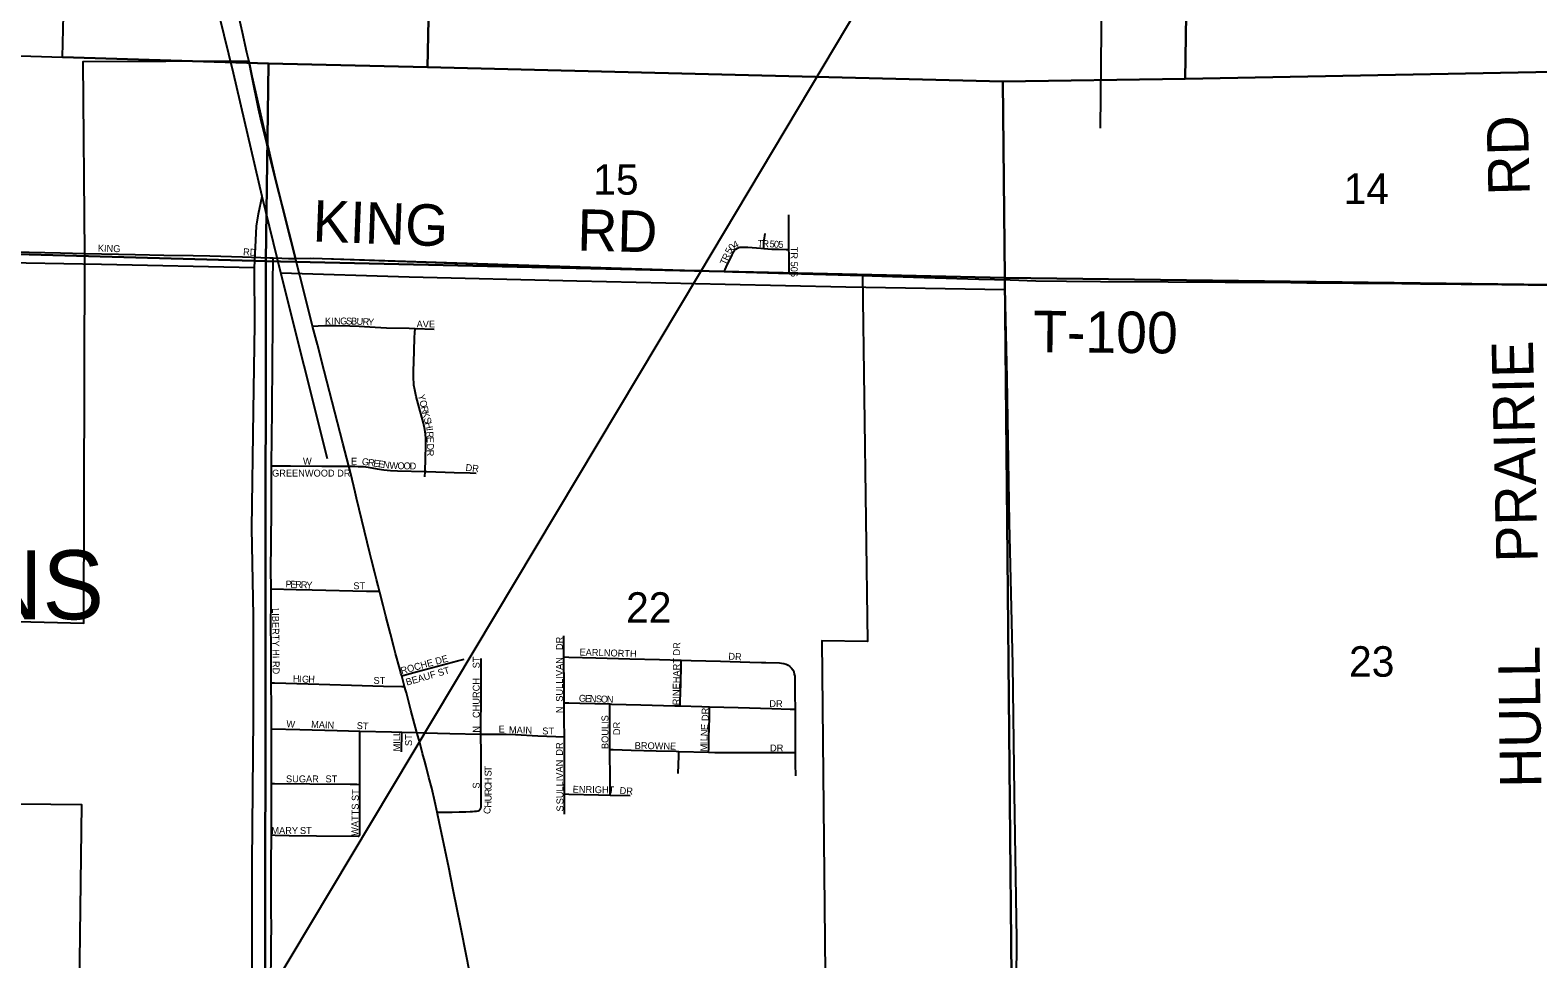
# Model space of a CAD drawing. Extents: x 1443599 to 1910620, y 1028088 to 1361369.
# Drawn here: x 1635252 to 1646176, y 1262715 to 1269443 of the extents above; entities that cross this region are included whole.
import ezdxf

# ---------------------------------------------------------------- set-up
doc = ezdxf.new("R2010")
doc.units = 0
for name, color, linetype in [('GM_X_City_Street', 7, 'Continuous'), ('GM_X_City_Street_Text', 7, 'Continuous'), ('GM_X_Corporation', 7, 'Continuous'), ('GM_X_Corporation_Text', 7, 'Continuous'), ('GM_X_Minor_River', 7, 'Continuous'), ('GM_X_Rail_Line', 7, 'Continuous'), ('GM_X_Section', 7, 'Continuous'), ('GM_X_Section_Text', 7, 'Continuous'), ('GM_X_State_Route', 7, 'Continuous'), ('GM_X_Township_Road', 7, 'Continuous'), ('GM_X_Township_Road_Text', 7, 'Continuous'), ('GM_X_Township_Subdivision', 7, 'Continuous'), ('GM_X_Township_Subdivision_Text', 7, 'Continuous')]:
    doc.layers.add(name, color=color, linetype=linetype)

msp = doc.modelspace()

# ---------------------------------------------------------------- linework, layer by layer
at = {"layer": 'GM_X_City_Street'}
for points in [[(1635648, 1267824), (1636013, 1267818), (1636220, 1267814), (1636433, 1267810), (1636555, 1267808), (1636790, 1267801), (1636988, 1267794), (1637012, 1267793)], [(1637002, 1266286), (1637002, 1266294), (1637004, 1266491), (1637006, 1266689), (1637006, 1266787), (1637009, 1266952), (1637008, 1267067), (1637010, 1267280), (1637010, 1267395), (1637011, 1267527), (1637011, 1267642), (1637012, 1267757), (1637012, 1267793)], [(1637299, 1267299), (1637339, 1267301), (1637388, 1267303), (1637470, 1267303), (1637569, 1267302), (1637635, 1267299), (1637751, 1267291), (1637833, 1267287), (1637998, 1267283), (1638041, 1267282)], [(1638114, 1266246), (1638120, 1266435), (1638120, 1266484), (1638117, 1266517), (1638113, 1266549), (1638101, 1266597), (1638071, 1266709), (1638050, 1266789), (1638039, 1266837), (1638033, 1266870), (1638031, 1266886), (1638030, 1266920), (1638030, 1266970), (1638035, 1267118), (1638038, 1267217), (1638040, 1267250), (1638041, 1267282)], [(1638041, 1267282), (1638180, 1267278)], [(1636998, 1265397), (1636997, 1265538), (1636999, 1265719), (1637001, 1265982), (1637001, 1266163), (1637002, 1266286)], [(1637002, 1266286), (1637138, 1266286), (1637365, 1266284), (1637560, 1266285)], [(1637560, 1266285), (1637604, 1266284), (1637629, 1266283), (1637652, 1266282), (1637668, 1266281), (1637701, 1266277), (1637767, 1266266), (1637815, 1266258), (1637864, 1266254), (1637913, 1266251), (1638114, 1266246)], [(1638113, 1266207), (1638114, 1266246)], [(1638114, 1266246), (1638127, 1266246), (1638325, 1266239), (1638441, 1266235), (1638484, 1266234)], [(1636999, 1264716), (1636998, 1264766), (1636998, 1264946), (1636997, 1265160), (1636998, 1265275), (1636998, 1265397)], [(1636998, 1265397), (1637180, 1265392), (1637295, 1265389), (1637688, 1265379), (1637753, 1265378), (1637783, 1265378)], [(1639120, 1264902), (1639120, 1265038), (1639119, 1265055)], [(1637944, 1264765), (1637978, 1264775), (1638059, 1264797), (1638348, 1264875), (1638397, 1264887)], [(1638518, 1264344), (1638518, 1264460), (1638519, 1264543), (1638519, 1264692), (1638519, 1264792), (1638519, 1264842), (1638520, 1264875), (1638520, 1264892)], [(1639120, 1264902), (1639155, 1264901), (1639352, 1264896), (1639598, 1264888), (1639811, 1264883), (1639970, 1264879)], [(1639122, 1264571), (1639121, 1264692), (1639120, 1264890), (1639120, 1264902)], [(1639962, 1264548), (1639963, 1264580), (1639967, 1264711), (1639970, 1264842), (1639970, 1264879)], [(1639970, 1264879), (1640041, 1264877), (1640254, 1264871), (1640467, 1264865), (1640550, 1264863), (1640582, 1264861), (1640681, 1264859), (1640697, 1264858), (1640713, 1264855), (1640729, 1264850), (1640744, 1264843), (1640757, 1264834), (1640768, 1264822), (1640778, 1264809), (1640785, 1264794), (1640789, 1264778), (1640792, 1264762), (1640793, 1264745), (1640793, 1264630), (1640794, 1264524)], [(1636999, 1264716), (1637022, 1264715), (1637266, 1264708), (1637580, 1264699), (1637812, 1264691), (1637946, 1264689), (1637965, 1264689)], [(1637001, 1264381), (1637000, 1264453), (1637000, 1264535), (1636999, 1264716)], [(1639122, 1264571), (1639154, 1264570), (1639236, 1264568), (1639453, 1264562)], [(1639123, 1264324), (1639122, 1264444), (1639122, 1264571)], [(1639453, 1264232), (1639453, 1264434), (1639453, 1264532), (1639453, 1264562)], [(1639453, 1264562), (1639465, 1264561), (1639678, 1264556), (1639923, 1264549), (1639962, 1264548)], [(1639962, 1264548), (1640120, 1264543), (1640175, 1264542)], [(1640168, 1264212), (1640169, 1264237), (1640170, 1264318), (1640175, 1264462), (1640175, 1264510), (1640175, 1264542)], [(1640175, 1264542), (1640382, 1264535), (1640627, 1264529), (1640758, 1264525), (1640794, 1264524)], [(1640794, 1264524), (1640795, 1264417), (1640794, 1264210)], [(1637000, 1263986), (1637000, 1264042), (1637000, 1264206), (1637001, 1264381)], [(1637001, 1264381), (1637207, 1264376), (1637476, 1264369), (1637640, 1264365)], [(1637640, 1264365), (1637871, 1264359), (1637944, 1264357)], [(1637640, 1263979), (1637640, 1264037), (1637640, 1264348), (1637640, 1264365)], [(1637943, 1264216), (1637944, 1264357)], [(1637944, 1264357), (1638055, 1264355)], [(1638055, 1264355), (1638114, 1264353), (1638293, 1264348), (1638518, 1264344)], [(1638200, 1263779), (1638311, 1263779), (1638360, 1263780), (1638392, 1263781), (1638409, 1263781), (1638441, 1263782), (1638456, 1263783), (1638471, 1263784), (1638487, 1263785), (1638499, 1263788), (1638508, 1263792), (1638513, 1263798), (1638518, 1263807), (1638519, 1263817), (1638520, 1263833), (1638520, 1263849), (1638520, 1263866), (1638520, 1263882), (1638520, 1263897), (1638519, 1263960), (1638519, 1264008), (1638519, 1264073), (1638520, 1264154), (1638519, 1264235), (1638518, 1264308), (1638518, 1264344)], [(1638518, 1264344), (1638522, 1264344), (1638702, 1264342), (1638768, 1264340), (1638931, 1264330), (1639062, 1264326), (1639123, 1264324)], [(1639124, 1263910), (1639124, 1263979), (1639123, 1264178), (1639123, 1264324)], [(1639454, 1263901), (1639454, 1263931), (1639454, 1264045), (1639453, 1264191), (1639453, 1264232)], [(1639453, 1264232), (1639477, 1264231), (1639607, 1264227), (1639787, 1264223), (1639934, 1264219), (1639952, 1264218)], [(1639948, 1264059), (1639951, 1264185), (1639952, 1264218)], [(1639952, 1264218), (1640168, 1264212)], [(1640168, 1264212), (1640212, 1264211), (1640794, 1264210)], [(1640794, 1264210), (1640796, 1264127), (1640798, 1264041)], [(1637000, 1263613), (1637000, 1263729), (1637000, 1263926), (1637000, 1263986)], [(1637000, 1263986), (1637022, 1263986), (1637279, 1263983), (1637570, 1263980), (1637618, 1263980), (1637640, 1263979)], [(1637637, 1263607), (1637638, 1263608), (1637639, 1263609), (1637639, 1263611), (1637640, 1263613), (1637640, 1263677), (1637641, 1263776), (1637640, 1263939), (1637640, 1263979)], [(1639124, 1263910), (1639156, 1263909), (1639369, 1263904), (1639454, 1263901)], [(1639124, 1263764), (1639124, 1263910)], [(1639454, 1263901), (1639599, 1263898)], [(1636999, 1262839), (1637000, 1262938), (1636999, 1263069), (1636999, 1263432), (1637000, 1263580), (1637000, 1263613)], [(1637000, 1263613), (1637028, 1263612), (1637128, 1263610), (1637328, 1263607), (1637630, 1263605), (1637632, 1263605), (1637634, 1263605), (1637636, 1263606), (1637637, 1263607)], [(1636997, 1262472), (1636999, 1262839)]]:
    msp.add_lwpolyline(points, dxfattribs=at)
at = {"layer": 'GM_X_Corporation'}
for points in [[(1634297, 1265182), (1635641, 1265146), (1635648, 1267824), (1635636, 1269216), (1636837, 1269220), (1636858, 1269113), (1637030, 1268362), (1637175, 1267789), (1637285, 1267792), (1637450, 1267786), (1640280, 1267695), (1640751, 1267681), (1641282, 1267666), (1641318, 1265015), (1640989, 1265020), (1641015, 1262371)], [(1635610, 1262515), (1635626, 1263830), (1634274, 1263845)]]:
    msp.add_lwpolyline(points, dxfattribs=at)
at = {"layer": 'GM_X_Minor_River'}
for points in [[(1643037, 1271626), (1643026, 1270663), (1643011, 1269435), (1643004, 1268733)], [(1637406, 1266337), (1637069, 1267686), (1636933, 1268239), (1636726, 1269132), (1636521, 1269970), (1636439, 1270297)], [(1636861, 1262358), (1636861, 1262486), (1636861, 1263412), (1636871, 1264461), (1636871, 1265199), (1636859, 1265836), (1636871, 1266685), (1636879, 1267311), (1636877, 1267722), (1636893, 1268023), (1636906, 1268113), (1636933, 1268239)], [(1636877, 1267722), (1635768, 1267745), (1634949, 1267760)], [(1637069, 1267686), (1637999, 1267655), (1639213, 1267628), (1640288, 1267604), (1641163, 1267583), (1642314, 1267564), (1642328, 1266921), (1642346, 1265877), (1642369, 1264847), (1642383, 1263912), (1642399, 1262858), (1642393, 1262232)]]:
    msp.add_lwpolyline(points, dxfattribs=at)
at = {"layer": 'GM_X_Rail_Line'}
msp.add_lwpolyline([(1628024, 1247385), (1629402, 1249688), (1632328, 1254610), (1636988, 1262473), (1640104, 1267683), (1644118, 1274411), (1645800, 1277195), (1647368, 1279858), (1650566, 1285234), (1651910, 1287492), (1654331, 1291581), (1655752, 1293976)], dxfattribs=at)
at = {"layer": 'GM_X_Section'}
for points in [[(1643716, 1274422), (1648915, 1274524), (1648809, 1269125), (1647557, 1269165), (1643620, 1269091), (1643662, 1271713), (1643687, 1273004)], [(1635549, 1271885), (1638187, 1271829), (1638130, 1269174), (1636978, 1269202), (1635486, 1269247), (1635517, 1270567)], [(1638187, 1271829), (1643662, 1271713), (1643620, 1269091), (1642299, 1269070), (1638130, 1269174)], [(1631668, 1269369), (1635486, 1269247), (1636978, 1269202), (1636961, 1267769), (1631645, 1267919)], [(1636978, 1269202), (1638130, 1269174), (1642299, 1269070), (1642314, 1267649), (1636961, 1267769)], [(1643620, 1269091), (1647557, 1269165), (1647578, 1267582), (1642314, 1267649), (1642299, 1269070)], [(1631645, 1267919), (1636961, 1267769), (1636956, 1262451), (1631539, 1262566)], [(1642314, 1267649), (1642365, 1262332), (1636956, 1262451), (1636961, 1267769)], [(1642314, 1267649), (1647578, 1267582), (1647671, 1262188), (1642365, 1262332)]]:
    msp.add_lwpolyline(points, close=True, dxfattribs=at)
at = {"layer": 'GM_X_State_Route'}
for points in [[(1636836, 1269222), (1636823, 1269282), (1636791, 1269426), (1636754, 1269586)], [(1636975, 1268585), (1636964, 1268633), (1636928, 1268776), (1636907, 1268872), (1636858, 1269113), (1636836, 1269222)], [(1637082, 1268153), (1637030, 1268362), (1636975, 1268585)], [(1637175, 1267789), (1637109, 1268044), (1637082, 1268153)], [(1637607, 1266096), (1637575, 1266228), (1637560, 1266285), (1637518, 1266451), (1637382, 1266976), (1637333, 1267167), (1637299, 1267299), (1637240, 1267533), (1637175, 1267789)], [(1637973, 1264658), (1637965, 1264689), (1637944, 1264765), (1637938, 1264785), (1637930, 1264817), (1637899, 1264927), (1637887, 1264975), (1637863, 1265070), (1637829, 1265197), (1637809, 1265274), (1637785, 1265369), (1637783, 1265378), (1637773, 1265417), (1637761, 1265464), (1637749, 1265511), (1637726, 1265606), (1637714, 1265654), (1637695, 1265734), (1637617, 1266053), (1637607, 1266096)], [(1638112, 1264145), (1638096, 1264203), (1638075, 1264282), (1638055, 1264355), (1638011, 1264516), (1637978, 1264643), (1637973, 1264658)], [(1638232, 1263629), (1638218, 1263696), (1638200, 1263779), (1638184, 1263855), (1638162, 1263951), (1638142, 1264030), (1638122, 1264109), (1638112, 1264145)], [(1638472, 1262438), (1638467, 1262462), (1638414, 1262734), (1638373, 1262943), (1638318, 1263215), (1638286, 1263376), (1638232, 1263629)]]:
    msp.add_lwpolyline(points, dxfattribs=at)
at = {"layer": 'GM_X_Township_Road'}
for points in [[(1631677, 1267898), (1631947, 1267894), (1632088, 1267892), (1632318, 1267888), (1632534, 1267883), (1632639, 1267882), (1632889, 1267878), (1633056, 1267876), (1633270, 1267873), (1633499, 1267870), (1633696, 1267868), (1634110, 1267860), (1634714, 1267847), (1634985, 1267841), (1635245, 1267834), (1635472, 1267830), (1635648, 1267824)], [(1637012, 1267793), (1637076, 1267791), (1637125, 1267790), (1637175, 1267789)], [(1637175, 1267789), (1637303, 1267791), (1637500, 1267784), (1638054, 1267765), (1638251, 1267757), (1638487, 1267750), (1638819, 1267739), (1639167, 1267729), (1639337, 1267724), (1639593, 1267716), (1639803, 1267710), (1639994, 1267705), (1640062, 1267703), (1640115, 1267701), (1640190, 1267698), (1640280, 1267695)], [(1640280, 1267695), (1640341, 1267693), (1640551, 1267687), (1640751, 1267681)], [(1640751, 1267681), (1641106, 1267671), (1641282, 1267666)], [(1641282, 1267666), (1641424, 1267662), (1641729, 1267652), (1642126, 1267640), (1642352, 1267634), (1642539, 1267628), (1642762, 1267624), (1643008, 1267621), (1643498, 1267620), (1643911, 1267618), (1644387, 1267614), (1644502, 1267612), (1644840, 1267610), (1645054, 1267609), (1645326, 1267605), (1645914, 1267600), (1646107, 1267598), (1646216, 1267597), (1646246, 1267596)]]:
    msp.add_lwpolyline(points, dxfattribs=at)
at = {"layer": 'GM_X_Township_Subdivision'}
for points in [[(1640750, 1267853), (1640749, 1267899), (1640749, 1268034), (1640750, 1268106)], [(1640567, 1267862), (1640568, 1267887), (1640568, 1267904), (1640570, 1267922), (1640572, 1267938), (1640575, 1267954), (1640578, 1267971)], [(1640280, 1267695), (1640287, 1267709), (1640296, 1267726), (1640338, 1267816), (1640345, 1267831), (1640349, 1267837), (1640354, 1267845), (1640359, 1267851), (1640365, 1267857), (1640377, 1267864), (1640387, 1267868), (1640395, 1267871)], [(1640395, 1267871), (1640418, 1267872), (1640451, 1267871), (1640547, 1267863), (1640567, 1267862)], [(1640567, 1267862), (1640627, 1267857), (1640675, 1267856), (1640730, 1267854), (1640750, 1267853)], [(1640751, 1267681), (1640751, 1267692), (1640752, 1267761), (1640751, 1267821), (1640750, 1267853)]]:
    msp.add_lwpolyline(points, dxfattribs=at)

# ---------------------------------------------------------------- texts
at = {"layer": 'GM_X_City_Street_Text'}
for s, rotation, p in [('KING', 358.3643, (1635742, 1267839)), ('RD', 356.9884, (1636794, 1267813)), ('K', 359.9781, (1637388, 1267311)), ('I', 359.9563, (1637432, 1267311)), ('N', 359.9813, (1637454, 1267311)), ('G', 359.9781, (1637498, 1267311)), ('S', 359.0984, (1637541, 1267311)), ('B', 357.6191, (1637576, 1267311)), ('U', 357.2664, (1637616, 1267309)), ('R', 357.2719, (1637660, 1267307)), ('Y', 357.2664, (1637699, 1267305)), ('AVE', 0, (1638052, 1267289)), ('Y', 283.9726, (1638061, 1266798)), ('O', 283.9726, (1638072, 1266756)), ('R', 283.9761, (1638082, 1266713)), ('K', 283.9726, (1638092, 1266674)), ('S', 283.9846, (1638103, 1266632)), ('H', 282.8275, (1638111, 1266598)), ('I', 277.1901, (1638121, 1266556)), ('R', 272.672, (1638123, 1266535)), ('E', 272.1312, (1638125, 1266496)), ('D', 270.7651, (1638127, 1266448)), ('W', 0, (1637229, 1266295)), ('E', 0, (1637577, 1266295)), ('G', 351.7524, (1637653, 1266295)), ('R', 351.7394, (1637697, 1266289)), ('E', 351.7575, (1637736, 1266283)), ('E', 351.7462, (1637771, 1266278)), ('N', 351.987, (1637806, 1266273)), ('W', 356.9282, (1637854, 1266266)), ('O', 358.6979, (1637913, 1266263)), ('O', 358.6668, (1637957, 1266262)), ('D', 358.6753, (1638001, 1266261)), ('R', 270.0243, (1638127, 1266404)), ('DR', 353.6679, (1638405, 1266251)), ('GREENWOOD DR', 0, (1637005, 1266209)), ('P', 357.4309, (1637102, 1265406)), ('E', 357.4341, (1637137, 1265405)), ('R', 357.425, (1637172, 1265403)), ('R', 357.4328, (1637212, 1265401)), ('Y', 357.6359, (1637252, 1265399)), ('ST', 0, (1637594, 1265393)), ('LIBERTY HI RD', 270.5794, (1637005, 1265256)), ('DR', 90, (1639112, 1264952)), ('RINEHART DR', 89.3771, (1639957, 1264552)), ('ROCHE DE', 15.2529, (1637944, 1264777)), ('ST', 90, (1638509, 1264820)), ('SULLIVAN', 90, (1639112, 1264578)), ('EARL', 358.4097, (1639232, 1264913)), ('NORTH', 357.6154, (1639408, 1264909)), ('DR', 356.989, (1640310, 1264883)), ('H', 357.7478, (1637155, 1264720)), ('I', 357.7269, (1637199, 1264718)), ('G', 358.0675, (1637221, 1264717)), ('H', 359.6662, (1637267, 1264716)), ('BEAUF ST', 16.1865, (1637982, 1264694)), ('ST', 0, (1637740, 1264707)), ('CHURCH', 90, (1638509, 1264460)), ('G', 357.7924, (1639227, 1264579)), ('E', 357.806, (1639271, 1264577)), ('N', 357.7915, (1639306, 1264576)), ('S', 357.7951, (1639350, 1264574)), ('O', 357.7924, (1639386, 1264573)), ('N', 358.7767, (1639430, 1264571)), ('DR', 0, (1640608, 1264539)), ('W', 355.6039, (1637107, 1264394)), ('MAIN', 357.5647, (1637287, 1264390)), ('N', 90, (1639112, 1264495)), ('BOULIS', 90, (1639442, 1264235)), ('DR', 90, (1640168, 1264438)), ('ST', 356.4254, (1637617, 1264381)), ('MILL', 90, (1637933, 1264218)), ('ST', 90, (1638019, 1264257)), ('N', 90, (1638509, 1264354)), ('E', 0, (1638646, 1264355)), ('MAIN', 358.7818, (1638721, 1264350)), ('ST', 0, (1638963, 1264341)), ('DR', 90, (1639527, 1264336)), ('L', 89.153, (1640159, 1264292)), ('N', 87.6605, (1640160, 1264327)), ('E', 87.4036, (1640162, 1264371)), ('DR', 90, (1639112, 1264187)), ('BROWNE', 359.0456, (1639632, 1264236)), ('I', 89.9553, (1640159, 1264270)), ('M', 89.9454, (1640159, 1264218)), ('DR', 0, (1640613, 1264218)), ('T', 89.9956, (1638595, 1264072)), ('SULLIVAN', 90.7341, (1639116, 1263835)), ('SUGAR', 0, (1637106, 1263994)), ('ST', 0, (1637392, 1263994)), ('S', 89.9956, (1638595, 1264037)), ('H', 89.9928, (1638595, 1263980)), ('WATTS ST', 89.1889, (1637629, 1263606)), ('S', 90, (1638509, 1263949)), ('C', 89.994, (1638595, 1263940)), ('R', 89.994, (1638595, 1263900)), ('U', 89.6662, (1638595, 1263856)), ('ENRIGHT', 359.0613, (1639183, 1263919)), ('DR', 356.8101, (1639522, 1263910)), ('C', 73.0937, (1638579, 1263759)), ('H', 87.4933, (1638593, 1263810)), ('S', 90, (1639116, 1263782)), ('MARY', 0, (1637000, 1263620)), ('ST', 0, (1637207, 1263620))]:
    msp.add_text(s, height=50, rotation=rotation, dxfattribs=at).set_placement(p)
at = {"layer": 'GM_X_Corporation_Text'}
msp.add_text('HASKINS', height=500, rotation=0, dxfattribs=at).set_placement((1632852, 1265175))
at = {"layer": 'GM_X_Section_Text'}
for s, p in [('15', (1639332, 1268251)), ('14', (1644769, 1268184)), ('22', (1639570, 1265150)), ('23', (1644808, 1264759))]:
    msp.add_text(s, height=221, rotation=0, dxfattribs=at).set_placement(p)
at = {"layer": 'GM_X_Township_Road_Text'}
for s, rotation, p in [('RD', 91.4451, (1646118, 1268250)), ('KING', 357.8175, (1637296, 1267913)), ('RD', 358.5237, (1639214, 1267847)), ('T-100', 359.4383, (1642518, 1267111)), ('PRAIRIE', 91.2375, (1646175, 1265591)), ('HULL', 90.7676, (1646202, 1263957))]:
    msp.add_text(s, height=300, rotation=rotation, dxfattribs=at).set_placement(p)
at = {"layer": 'GM_X_Township_Subdivision_Text'}
for s, rotation, p in [('R', 65.4013, (1640307, 1267769)), ('5', 62.5832, (1640328, 1267817)), ('0', 45.7727, (1640340, 1267841)), ('4', 26.579, (1640358, 1267860)), ('T', 356.8293, (1640521, 1267874)), ('R', 356.8366, (1640556, 1267873)), ('5', 356.8444, (1640609, 1267870)), ('0', 356.8132, (1640640, 1267868)), ('5', 359.2323, (1640673, 1267866)), ('TR 506', 270, (1640763, 1267874)), ('T', 65.4271, (1640292, 1267737))]:
    msp.add_text(s, height=50, rotation=rotation, dxfattribs=at).set_placement(p)

doc.saveas('drawing.dxf')
